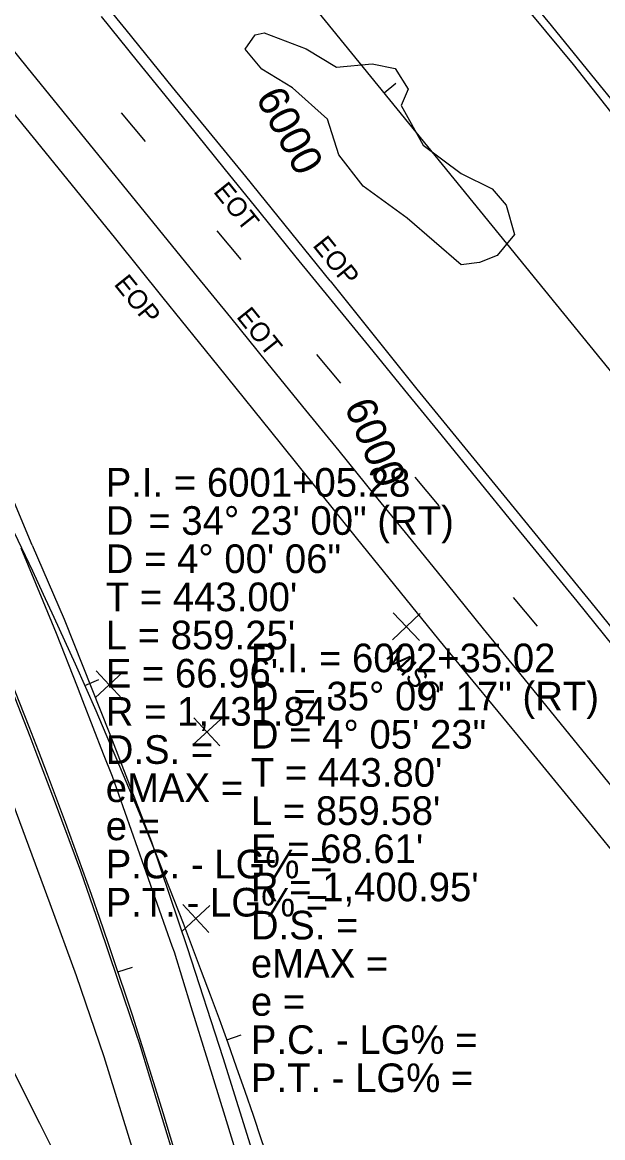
# Model space of a CAD drawing. Extents: x 2132221 to 2141942, y 535736 to 547298.
# Drawn here: x 2137049.2 to 2137201.1, y 541556.1 to 541848.3 of the extents above; entities that cross this region are included whole.
import ezdxf

# ---------------------------------------------------------------- set-up
doc = ezdxf.new("R2010")
doc.units = 0
for name, color, linetype in [('RD_EX_Misc', 7, 'Continuous'), ('RD_EX_Misc_txCode', 7, 'Continuous'), ('RD_EX_Road', 7, 'Continuous'), ('RD_EX_Road_txCode', 7, 'Continuous'), ('RD_EX_VEG', 7, 'Continuous'), ('RD_HC_Cl', 7, 'Continuous'), ('RD_HC_Data', 7, 'Continuous'), ('RD_HC_Data_Tic', 7, 'Continuous'), ('RD_HC_TX_Sta50', 7, 'Continuous')]:
    doc.layers.add(name, color=color, linetype=linetype)

msp = doc.modelspace()

# ---------------------------------------------------------------- linework, layer by layer
at = {"layer": 'RD_EX_Misc'}
for p, q in [((2137075.04, 541824.56), (2137081.33, 541817.03)), ((2137100.05, 541793.61), (2137106.35, 541786.09)), ((2137126.2, 541761.26), (2137132.5, 541753.73)), ((2137151.9, 541729.12), (2137158.19, 541721.6)), ((2137177.71, 541697.61), (2137184, 541690.08)), ((2137146.04, 541686.53), (2137153.34, 541693.37)), ((2137146.27, 541693.6), (2137153.11, 541686.3)), ((2137068.2, 541671.33), (2137075.55, 541678.12)), ((2137068.48, 541678.4), (2137075.26, 541671.05)), ((2137093.81, 541658.96), (2137101.15, 541665.74)), ((2137094.09, 541666.03), (2137100.87, 541658.68)), ((2137090.89, 541610.1), (2137098.24, 541616.88)), ((2137091.17, 541617.16), (2137097.95, 541609.81))]:
    msp.add_line(p, q, dxfattribs=at)
for points in [[(2137178.12, 541859.07), (2137187.59, 541847.44), (2137197.05, 541835.8), (2137206.52, 541824.16)], [(2137040.84, 541848.2), (2137050.3, 541836.56), (2137059.76, 541824.91), (2137069.22, 541813.27), (2137078.67, 541801.63), (2137084.72, 541794.19), (2137094.18, 541782.55), (2137103.64, 541770.91), (2137113.09, 541759.27), (2137122.55, 541747.62), (2137132.01, 541735.98), (2137141.47, 541724.34), (2137150.93, 541712.7), (2137160.39, 541701.06), (2137169.85, 541689.41), (2137179.3, 541677.77), (2137188.76, 541666.13), (2137198.22, 541654.49), (2137207.68, 541642.85)], [(2137069.8, 541849.79), (2137079.24, 541838.13), (2137083.05, 541833.42), (2137092.49, 541821.75), (2137101.92, 541810.09), (2137111.36, 541798.43), (2137120.8, 541786.76), (2137130.28, 541775.14), (2137139.76, 541763.51), (2137149.24, 541751.89), (2137158.72, 541740.26), (2137168.2, 541728.64), (2137177.67, 541717.01), (2137187.15, 541705.39), (2137194.33, 541696.59), (2137203.8, 541684.96)], [(2137048.78, 541710.61), (2137054.51, 541696.75), (2137058.04, 541688.22), (2137063.49, 541674.25), (2137064.91, 541670.6), (2137070.36, 541656.62), (2137072.65, 541650.74), (2137077.65, 541636.59), (2137082.64, 541622.45), (2137083.35, 541620.45), (2137088.34, 541606.3), (2137088.89, 541604.74), (2137093.32, 541590.4), (2137097.74, 541576.07), (2137102.16, 541561.74), (2137105.87, 541549.74)], [(2137045.67, 541675.27), (2137051.1, 541661.29), (2137052.46, 541657.79), (2137057.74, 541643.75), (2137063.02, 541629.71), (2137064.42, 541626), (2137069.24, 541611.8), (2137074.07, 541597.6), (2137078.9, 541583.4), (2137079.84, 541580.63), (2137084.19, 541566.28), (2137088.55, 541551.92)]]:
    msp.add_lwpolyline(points, dxfattribs=at)
at = {"layer": 'RD_EX_Road'}
for points in [[(2136707.76, 542424.02), (2136729, 542399.05), (2136756.88, 542366.08), (2136784.05, 542334.02), (2136809.93, 542303.58), (2136839.08, 542269.1), (2136860.77, 542243.12), (2136882.71, 542216.67), (2136907.37, 542186.91), (2136924.47, 542166.25), (2136945.23, 542140.83), (2136969.19, 542111.86), (2136995.45, 542079.97), (2137017.76, 542052.48), (2137039.43, 542026.33), (2137063.92, 541996), (2137080.05, 541976.19), (2137096.8, 541955.76), (2137112.6, 541936.21), (2137134.84, 541908.64), (2137151.98, 541887.74), (2137171.65, 541863.54), (2137193.35, 541837.19)], [(2137129.75, 541780.57), (2137107.7, 541807.88), (2137088.48, 541831.26), (2137076.31, 541846.31), (2137059.57, 541866.89), (2137038.31, 541893.09), (2137028.99, 541904.49), (2137023.6, 541911.43), (2137008.32, 541930.08), (2136988.29, 541954.48), (2136973.96, 541972.2), (2136960.6, 541988.74), (2136942.64, 542011.01), (2136927.03, 542029.72), (2136910.37, 542050.05), (2136891.8, 542072.92), (2136874.04, 542094.49), (2136856.69, 542115.76), (2136841.62, 542134.18), (2136823.08, 542157.17)], [(2137030.8, 541844.01), (2137053.94, 541815.77), (2137073.56, 541791.56), (2137085.91, 541776.07), (2137100.38, 541758.24)], [(2137193.35, 541837.19), (2137212.91, 541812.44), (2137235.27, 541784.87), (2137254.4, 541760.88), (2137274.02, 541736.87), (2137295.29, 541710.97), (2137313.63, 541688.15), (2137334.61, 541662.71), (2137358.33, 541633.36), (2137376.02, 541611.54), (2137393.61, 541589.72), (2137411.3, 541568), (2137437.87, 541535.36), (2137465.67, 541501.18), (2137489.75, 541471.68), (2137511.61, 541444.85), (2137530.92, 541421.07), (2137548.19, 541400.06), (2137569.12, 541374.18), (2137589.5, 541349.39), (2137612.36, 541321.32), (2137632.5, 541296.04), (2137648.27, 541276.75), (2137665.39, 541255.65)], [(2137129.75, 541780.57), (2137152.42, 541752.13), (2137176.05, 541723.37), (2137199.18, 541694.95), (2137221.19, 541667.61), (2137243.48, 541640.3), (2137267.28, 541610.96), (2137291.46, 541581.15), (2137312.24, 541555.53), (2137336.72, 541525.3), (2137359.73, 541497.32), (2137378.4, 541474.19), (2137407.74, 541438.19), (2137425.75, 541416.17), (2137446.57, 541390.46), (2137472.54, 541358.27), (2137492.89, 541333.37), (2137514.29, 541307.17), (2137539.52, 541276.53), (2137564.39, 541245.78), (2137586.4, 541218.72), (2137608.31, 541191.93)], [(2137100.38, 541758.24), (2137116.65, 541738.05), (2137136.57, 541713.17), (2137158.12, 541686.61), (2137181.43, 541658.3), (2137199.12, 541636.62), (2137219.56, 541611.48), (2137227.67, 541601.79), (2137247.01, 541578.63), (2137263.16, 541558.53), (2137284.05, 541532.79), (2137307.73, 541503.58), (2137328.85, 541477.64), (2137348.35, 541453.76), (2137369.96, 541427.39), (2137389.21, 541403.83), (2137412.54, 541375.44), (2137433.11, 541350), (2137456.28, 541321.75), (2137474.25, 541299.22), (2137503.28, 541263.26), (2137525.6, 541235.47)], [(2137051.72, 541711.33), (2137039.17, 541741.24)], [(2137051.72, 541711.33), (2137060.08, 541691.88), (2137072.03, 541661.82), (2137083, 541633.57), (2137092.36, 541605.91), (2137101.68, 541577.11), (2137109.68, 541551.35), (2137116.45, 541527.85), (2137122.39, 541504.85), (2137130.92, 541470.34), (2137135.22, 541450.02), (2137139.62, 541428.45), (2137143.38, 541409.81), (2137148.36, 541380.69), (2137152.26, 541355.85), (2137155.18, 541335.32), (2137157.69, 541311.99), (2137160.31, 541289.06), (2137161.83, 541270.24), (2137163.12, 541253.19), (2137164.61, 541228.85)], [(2137026.6, 541693.64), (2137035.81, 541671.39), (2137046.1, 541645.29), (2137056.39, 541617.43), (2137063.26, 541598.52), (2137070.48, 541577.29), (2137078.29, 541552.17), (2137086.91, 541521.66), (2137093.46, 541497.68), (2137100.65, 541468.48), (2137106.62, 541441.3), (2137111.28, 541418.69), (2137116.26, 541390.82), (2137119.99, 541367.72), (2137123.2, 541346.58), (2137125.73, 541329.98), (2137128.98, 541305.14), (2137131.05, 541279.98), (2137135.49, 541218.79)]]:
    msp.add_lwpolyline(points, dxfattribs=at)
at = {"layer": 'RD_EX_VEG'}
msp.add_lwpolyline([(2137164.08, 541784.72), (2137149.92, 541796.94), (2137138.4, 541805.32), (2137132.07, 541813.52), (2137129.04, 541822.94), (2137119.92, 541831.14), (2137111.84, 541836.04), (2137107.51, 541841.28), (2137110.14, 541845.03), (2137112.46, 541845.53), (2137123.45, 541841.29), (2137131.44, 541836.49), (2137140.79, 541837.41), (2137146.8, 541836.14), (2137150.16, 541830.74), (2137148.38, 541826.48), (2137154.15, 541816.09), (2137164.07, 541808.63), (2137172.19, 541804.69), (2137175.87, 541800.34), (2137178, 541792.67), (2137173.48, 541787.17), (2137168.9, 541785.31)], close=True, dxfattribs=at)
msp.add_lwpolyline([(2137046.92, 541573.23), (2137053.66, 541559.83), (2137060.4, 541546.43)], dxfattribs=at)
at = {"layer": 'RD_HC_Cl'}
msp.add_line((2136971.61, 542041.65), (2141699.63, 536226.46), dxfattribs=at)
for centre, radius, start, end in [((2135716.74, 541144.04), 1431.84, 1.67918, 36.06251), ((2135784.3, 541107.9), 1400.95, 1.32972, 36.48455)]:
    msp.add_arc(centre, radius, start, end, dxfattribs=at)
at = {"layer": 'RD_HC_Data_Tic'}
for p, q in [((2137143.86, 541829.8), (2137146.96, 541832.32)), ((2137065.56, 541674.5), (2137069.22, 541676.12)), ((2137074.21, 541599.48), (2137078, 541600.75)), ((2137074.21, 541599.48), (2137078, 541600.75)), ((2137102.71, 541581.68), (2137106.47, 541583.04))]:
    msp.add_line(p, q, dxfattribs=at)

# ---------------------------------------------------------------- texts
at = {"layer": 'RD_EX_Misc_txCode'}
for s, rotation, p in [('EOT', 308.7997, (2137099, 541803.86)), ('EOT', 308.7997, (2137105.04, 541771.09)), (' MISC', 313.1485, (2137142.84, 541683.35))]:
    msp.add_text(s, height=5, rotation=rotation, dxfattribs=at).set_placement(p)
at = {"layer": 'RD_EX_Road_txCode'}
for p in [(2137124.99, 541789.76), (2137072.96, 541779.61)]:
    msp.add_text('EOP', height=5, rotation=308.915, dxfattribs=at).set_placement(p)
at = {"layer": 'RD_HC_Data'}
for s, p in [('P.I. = 6001+05.28', (2137071, 541724)), ('    = 34%%d 23\' 00" (RT)', (2137071, 541714)), ('D', (2137071, 541714)), ('D = 4%%d 00\' 06"', (2137071, 541704)), ("T = 443.00'", (2137071, 541694)), ("L = 859.25'", (2137071, 541684)), ('P.I. = 6002+35.02', (2137109, 541678)), ("E = 66.96'", (2137071, 541674)), ('D', (2137109, 541668)), ('    = 35%%d 09\' 17" (RT)', (2137109, 541668)), ("R = 1,431.84'", (2137071, 541664)), ('D = 4%%d 05\' 23"', (2137109, 541658)), ('D.S. = ', (2137071, 541654)), ("T = 443.80'", (2137109, 541648)), ('eMAX = ', (2137071, 541644)), ("L = 859.58'", (2137109, 541638)), ('e = ', (2137071, 541634)), ("E = 68.61'", (2137109, 541628)), ('P.C. - LG% = ', (2137071, 541624)), ("R = 1,400.95'", (2137109, 541618)), ('P.T. - LG% = ', (2137071, 541614)), ('D.S. = ', (2137109, 541608)), ('eMAX = ', (2137109, 541598)), ('e = ', (2137109, 541588)), ('P.C. - LG% = ', (2137109, 541578)), ('P.T. - LG% = ', (2137109, 541568))]:
    msp.add_text(s, height=7.5, dxfattribs=at).set_placement(p)
at = {"layer": 'RD_HC_TX_Sta50'}
for rotation, p in [(297.9459, (2137110.11, 541828.6)), (292.5485, (2137133.37, 541747.75)), (292.5485, (2137133.37, 541747.75))]:
    msp.add_text('6000', height=8, rotation=rotation, dxfattribs=at).set_placement(p)

doc.saveas('drawing.dxf')
